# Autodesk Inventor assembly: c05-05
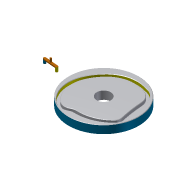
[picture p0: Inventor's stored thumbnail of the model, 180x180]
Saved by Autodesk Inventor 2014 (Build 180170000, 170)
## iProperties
Created: 2010-11
Part Number: c05-05
Document SubType Name: Assembly
Designer: Thom Tremblay
Author: Thom Tremblay
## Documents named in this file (3)
- C:\Inventor 2014 Essentials\Assemblies\Chapter 05\c05-05.iam
- C:\Inventor 2014 Essentials\Parts\Chapter 05\c05-05.ipt
- C:\Inventor 2014 Essentials\Parts\Chapter 05\c05-06.ipt
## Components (2 placed, 2 different names)
1. c05-05:1 — Mate:1
2. c05-06:1 — Mate:1
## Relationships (1: Mate 1)
- Mate:1: c05-05:1 ↔ c05-06:1
